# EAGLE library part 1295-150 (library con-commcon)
.800" BOARD SPACE 2mm CONNECTORS - HI TEMP 6 ROW 2mm- END OF STACK HEADER
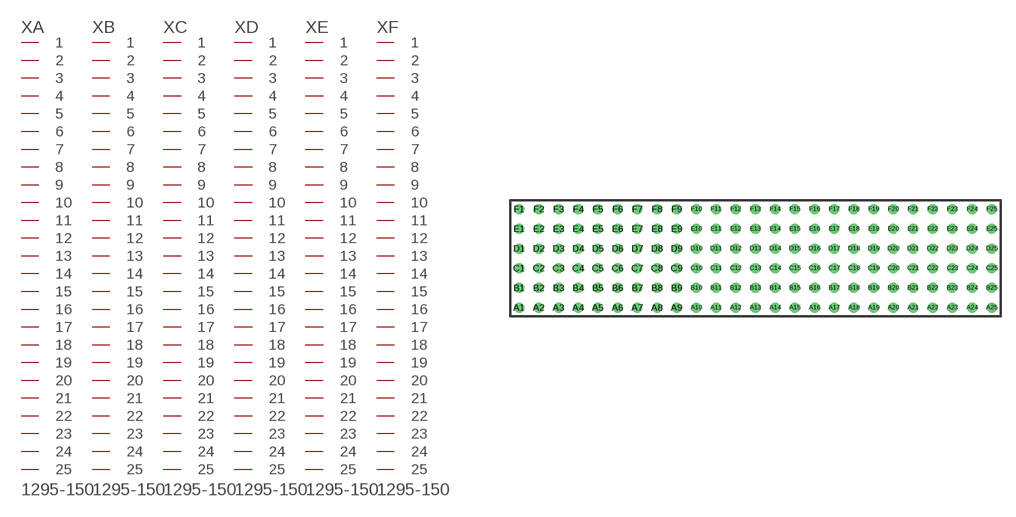
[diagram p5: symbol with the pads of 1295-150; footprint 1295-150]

Designator prefix X; gates A=PIN25 B=PIN25 C=PIN25 D=PIN25 E=PIN25 F=PIN25

## 1295-150 (OC_FARNELL: unknown; OC_NEWARK: unknown)  [1295-150]
A1  A:1  pas
A2  A:2  pas
A3  A:3  pas
A4  A:4  pas
A5  A:5  pas
A6  A:6  pas
A7  A:7  pas
A8  A:8  pas
A9  A:9  pas
A10  A:10  pas
A11  A:11  pas
A12  A:12  pas
A13  A:13  pas
A14  A:14  pas
A15  A:15  pas
A16  A:16  pas
A17  A:17  pas
A18  A:18  pas
A19  A:19  pas
A20  A:20  pas
A21  A:21  pas
A22  A:22  pas
A23  A:23  pas
A24  A:24  pas
A25  A:25  pas
B1  B:1  pas
B2  B:2  pas
B3  B:3  pas
B4  B:4  pas
B5  B:5  pas
B6  B:6  pas
B7  B:7  pas
B8  B:8  pas
B9  B:9  pas
B10  B:10  pas
B11  B:11  pas
B12  B:12  pas
B13  B:13  pas
B14  B:14  pas
B15  B:15  pas
B16  B:16  pas
B17  B:17  pas
B18  B:18  pas
B19  B:19  pas
B20  B:20  pas
B21  B:21  pas
B22  B:22  pas
B23  B:23  pas
B24  B:24  pas
B25  B:25  pas
C1  C:1  pas
C2  C:2  pas
C3  C:3  pas
C4  C:4  pas
C5  C:5  pas
C6  C:6  pas
C7  C:7  pas
C8  C:8  pas
C9  C:9  pas
C10  C:10  pas
C11  C:11  pas
C12  C:12  pas
C13  C:13  pas
C14  C:14  pas
C15  C:15  pas
C16  C:16  pas
C17  C:17  pas
C18  C:18  pas
C19  C:19  pas
C20  C:20  pas
C21  C:21  pas
C22  C:22  pas
C23  C:23  pas
C24  C:24  pas
C25  C:25  pas
D1  D:1  pas
D2  D:2  pas
D3  D:3  pas
D4  D:4  pas
D5  D:5  pas
D6  D:6  pas
D7  D:7  pas
D8  D:8  pas
D9  D:9  pas
D10  D:10  pas
D11  D:11  pas
D12  D:12  pas
D13  D:13  pas
D14  D:14  pas
D15  D:15  pas
D16  D:16  pas
D17  D:17  pas
D18  D:18  pas
D19  D:19  pas
D20  D:20  pas
D21  D:21  pas
D22  D:22  pas
D23  D:23  pas
D24  D:24  pas
D25  D:25  pas
E1  E:1  pas
E2  E:2  pas
E3  E:3  pas
E4  E:4  pas
E5  E:5  pas
E6  E:6  pas
E7  E:7  pas
E8  E:8  pas
E9  E:9  pas
E10  E:10  pas
E11  E:11  pas
E12  E:12  pas
E13  E:13  pas
E14  E:14  pas
E15  E:15  pas
E16  E:16  pas
E17  E:17  pas
E18  E:18  pas
E19  E:19  pas
E20  E:20  pas
E21  E:21  pas
E22  E:22  pas
E23  E:23  pas
E24  E:24  pas
E25  E:25  pas
F1  F:1  pas
F2  F:2  pas
F3  F:3  pas
F4  F:4  pas
F5  F:5  pas
F6  F:6  pas
F7  F:7  pas
F8  F:8  pas
F9  F:9  pas
F10  F:10  pas
F11  F:11  pas
F12  F:12  pas
F13  F:13  pas
F14  F:14  pas
F15  F:15  pas
F16  F:16  pas
F17  F:17  pas
F18  F:18  pas
F19  F:19  pas
F20  F:20  pas
F21  F:21  pas
F22  F:22  pas
F23  F:23  pas
F24  F:24  pas
F25  F:25  pas

## Footprint 1295-150 (pad centres in mm)
.800" BOARD SPACE 2mm CONNECTORS - HI TEMP 6 ROW 2mm- END OF STACK HEADER
drill 0.508 round: A1 -24,-5; A2 -22,-5; A3 -20,-5; A4 -18,-5; A5 -16,-5; A6 -14,-5; A7 -12,-5; A8 -10,-5; A9 -8,-5; A10 -6,-5; A11 -4,-5; A12 -2,-5; A13 0,-5; A14 2,-5; A15 4,-5; A16 6,-5; A17 8,-5; A18 10,-5; A19 12,-5; A20 14,-5; A21 16,-5; A22 18,-5; A23 20,-5; A24 22,-5; A25 24,-5; B1 -24,-3; B2 -22,-3; B3 -20,-3; B4 -18,-3; B5 -16,-3; B6 -14,-3; B7 -12,-3; B8 -10,-3; B9 -8,-3; B10 -6,-3; B11 -4,-3; B12 -2,-3; B13 0,-3; B14 2,-3; B15 4,-3; B16 6,-3; B17 8,-3; B18 10,-3; B19 12,-3; B20 14,-3; B21 16,-3; B22 18,-3; B23 20,-3; B24 22,-3; B25 24,-3; C1 -24,-1; C2 -22,-1; C3 -20,-1; C4 -18,-1; C5 -16,-1; C6 -14,-1; C7 -12,-1; C8 -10,-1; C9 -8,-1; C10 -6,-1; C11 -4,-1; C12 -2,-1; C13 0,-1; C14 2,-1; C15 4,-1; C16 6,-1; C17 8,-1; C18 10,-1; C19 12,-1; C20 14,-1; C21 16,-1; C22 18,-1; C23 20,-1; C24 22,-1; C25 24,-1; D1 -24,1; D2 -22,1; D3 -20,1; D4 -18,1; D5 -16,1; D6 -14,1; D7 -12,1; D8 -10,1; D9 -8,1; D10 -6,1; D11 -4,1; D12 -2,1; D13 0,1; D14 2,1; D15 4,1; D16 6,1; D17 8,1; D18 10,1; D19 12,1; D20 14,1; D21 16,1; D22 18,1; D23 20,1; D24 22,1; D25 24,1; E1 -24,3; E2 -22,3; E3 -20,3; E4 -18,3; E5 -16,3; E6 -14,3; E7 -12,3; E8 -10,3; E9 -8,3; E10 -6,3; E11 -4,3; E12 -2,3; E13 0,3; E14 2,3; E15 4,3; E16 6,3; E17 8,3; E18 10,3; E19 12,3; E20 14,3; E21 16,3; E22 18,3; E23 20,3; E24 22,3; E25 24,3; F1 -24,5; F2 -22,5; F3 -20,5; F4 -18,5; F5 -16,5; F6 -14,5; F7 -12,5; F8 -10,5; F9 -8,5; F10 -6,5; F11 -4,5; F12 -2,5; F13 0,5; F14 2,5; F15 4,5; F16 6,5; F17 8,5; F18 10,5; F19 12,5; F20 14,5; F21 16,5; F22 18,5; F23 20,5; F24 22,5; F25 24,5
